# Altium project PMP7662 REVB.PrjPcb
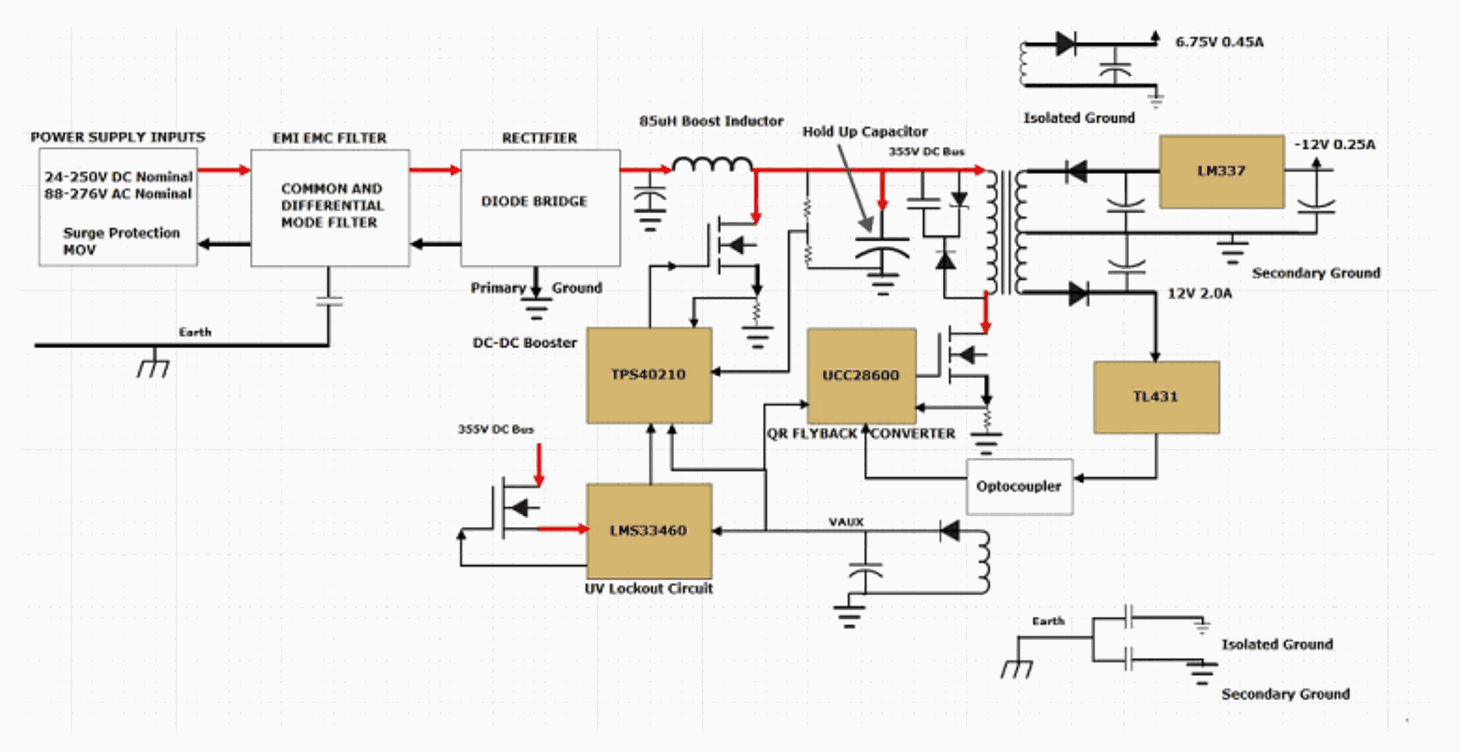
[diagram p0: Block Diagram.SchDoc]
CopyrightYear: 2014; PCB_Rev: A1; PRJ_Customer: Public Release; PRJ_Engineer: Sunil Dwivedi; PRJ_Number: TIDA-00127; PRJ_Title: TIDA-00127-PRPS; SCH_Rev: A1; TechSupport: http://www.ti.com/support
4 sheets, 166 parts. Net scope: flat (ports and power ports of the same name join across sheets).
Board file: PMP7662 REVB-1.PcbDoc
Sheets:
  Block Diagram.SchDoc
  Boost converter.SchDoc
  Fly back converter.SchDoc
  Hardware.SchDoc

## Sheet Block Diagram.SchDoc
size 431 x 279 mm; Date: Not shown in title block; ApprovedBy: Not shown in title block; CheckedBy: Not shown in title block; Author: Not shown in title block; CompanyName: Not shown in title block; Engineer: Not shown in title block; Organization: Not shown in title block; Address1: Not shown in title block; Address2: Not shown in title block; Address3: Not shown in title block; Address4: Not shown in title block; DocumentNumber: 1; Revision: Use project parameter SCH_Rev; SheetNumber: 1; SheetTotal: 4; PageSetup: Record=PageOptions|CenterHorizontal=True|CenterVertical=True|PrintScale=0.96|XCorrection=1.00|YCorrection=1.00|PrintKind=0|BorderSize=5000000|LeftOffset=0|BottomOffset=0|Orientation=2|PaperLength=1000|PaperWidth=1000|Scale=100|PaperSource=15|PrintQuality=600|MediaType=1|DitherType=10|PaperKind=A3|PrintScaleMode=1

## Sheet Boost converter.SchDoc
size 431 x 279 mm; Date: Not shown in title block; ApprovedBy: Not shown in title block; CheckedBy: Not shown in title block; Author: Not shown in title block; CompanyName: Not shown in title block; Engineer: Not shown in title block; Organization: Not shown in title block; Address1: Not shown in title block; Address2: Not shown in title block; Address3: Not shown in title block; Address4: Not shown in title block; DocumentNumber: 2; Revision: Use project parameter SCH_Rev; SheetNumber: 2; SheetTotal: 4; PageSetup: Record=PageOptions|CenterHorizontal=True|CenterVertical=True|PrintScale=1.00|XCorrection=1.00|YCorrection=1.00|PrintKind=0|BorderSize=5000000|LeftOffset=0|BottomOffset=0|Orientation=2|PaperLength=1000|PaperWidth=1000|Scale=100|PaperSource=15|PrintQuality=600|MediaType=1|DitherType=10|PaperKind=Letter|PrintScaleMode=1
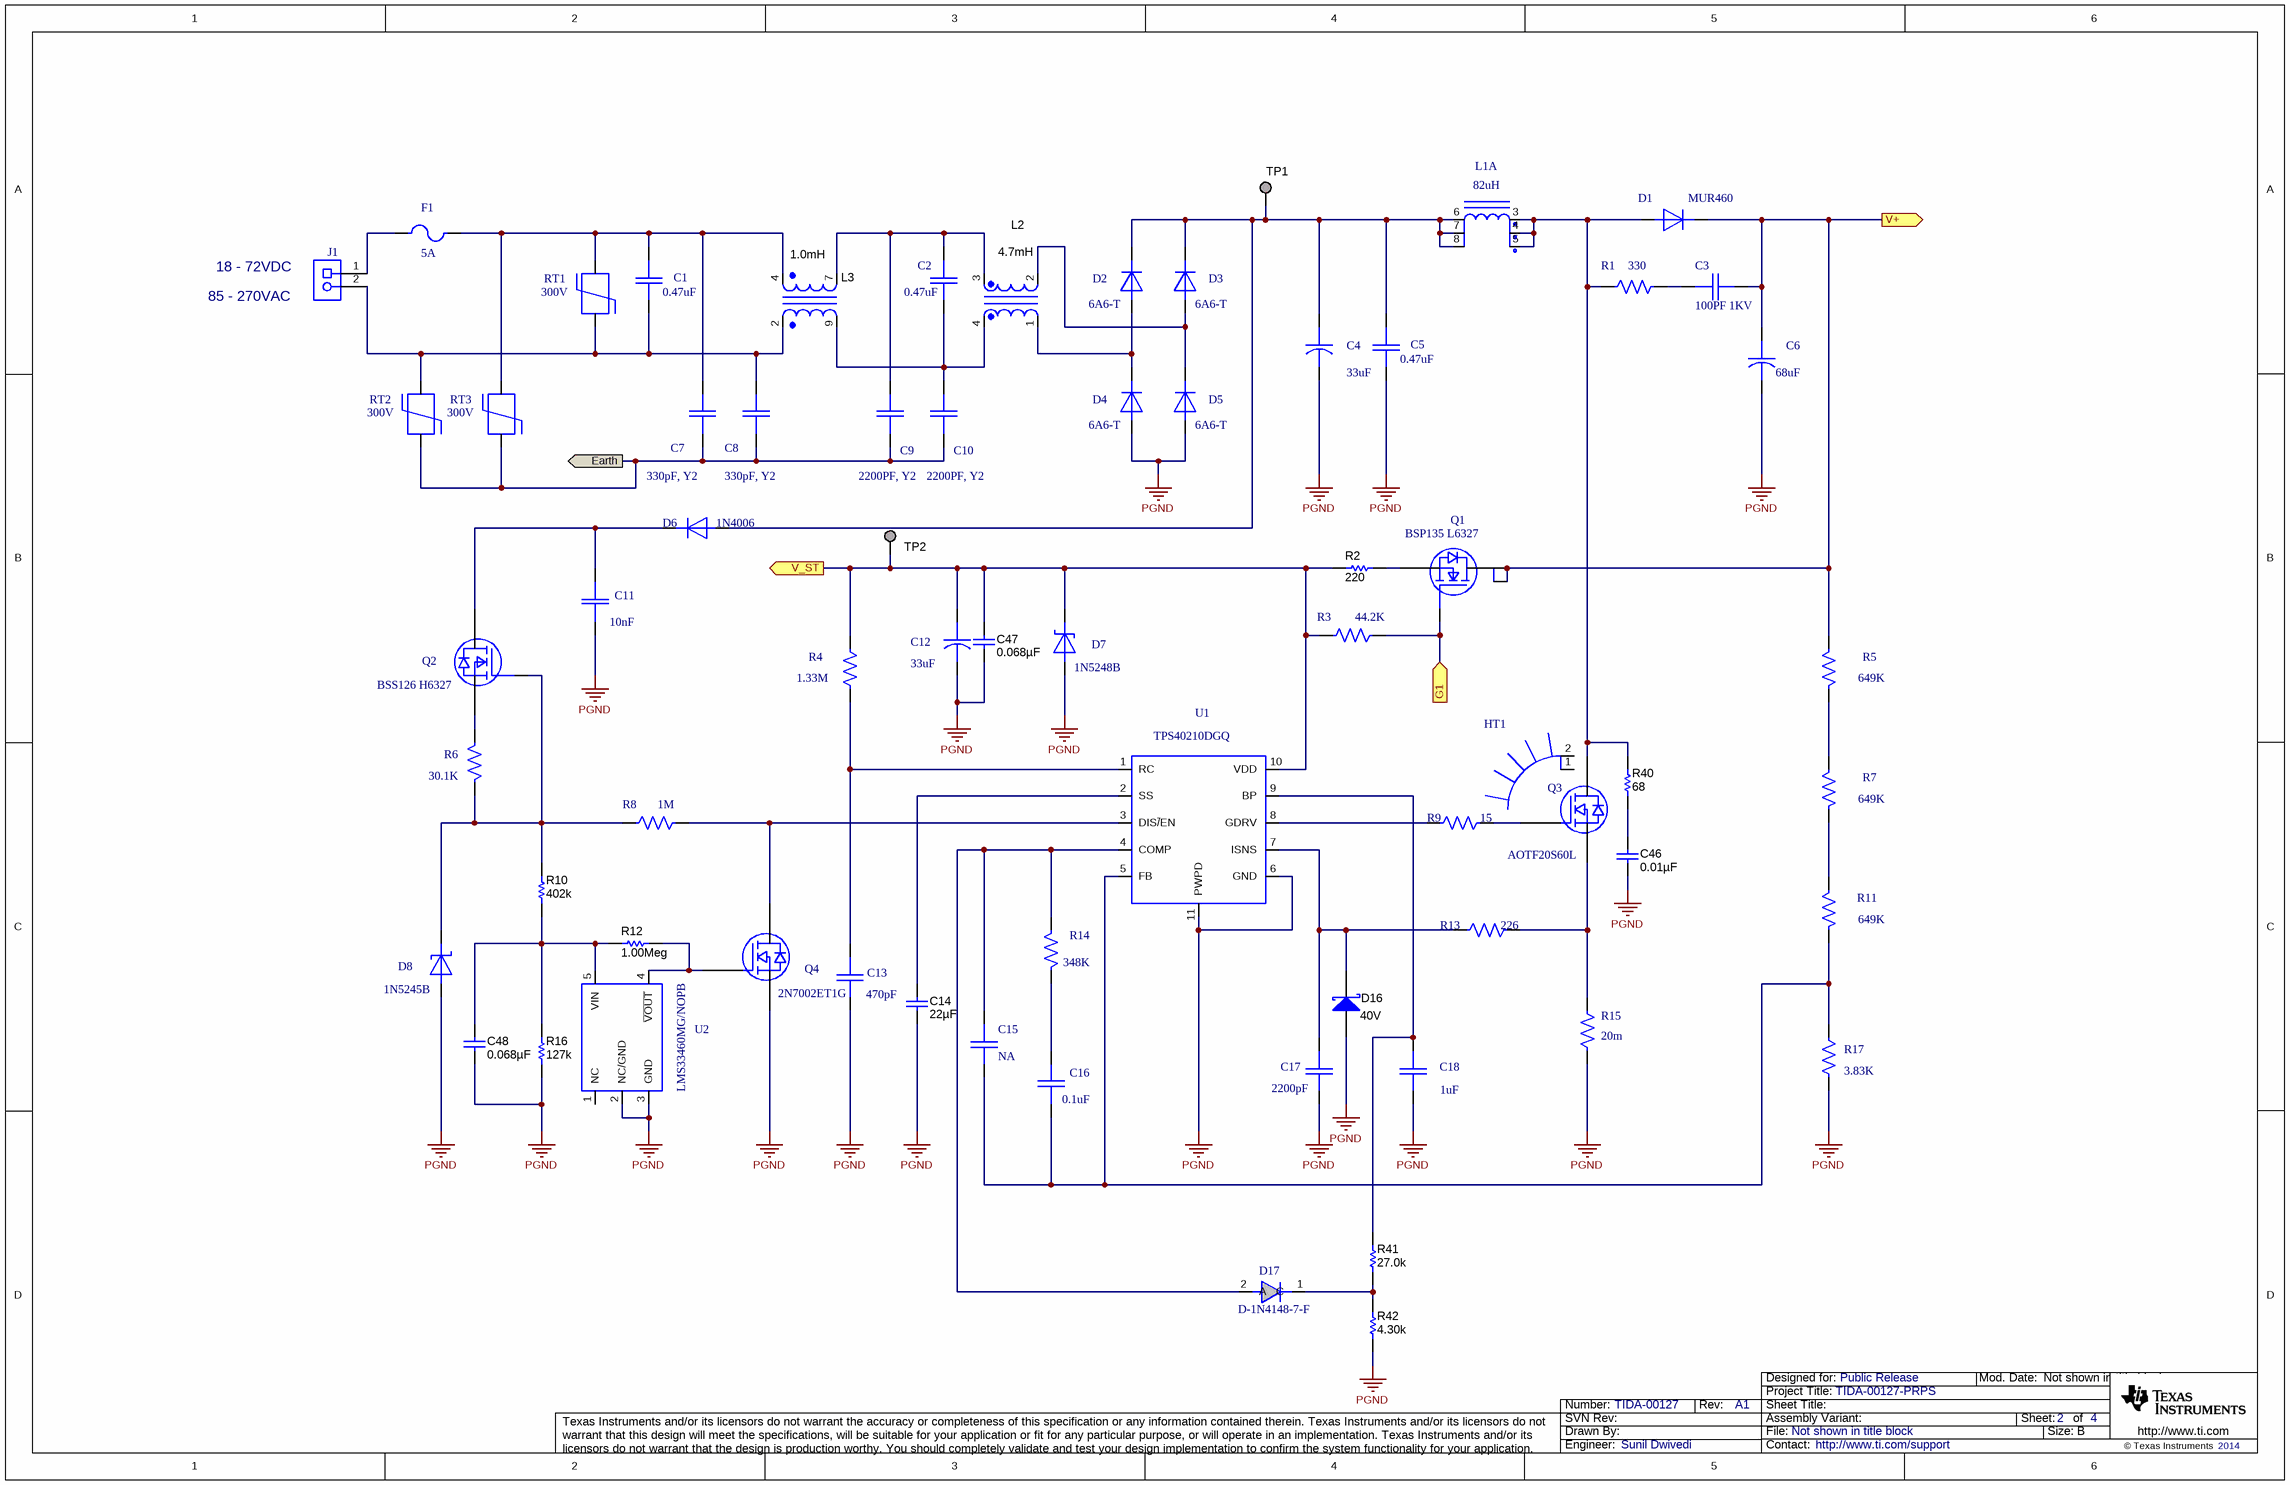
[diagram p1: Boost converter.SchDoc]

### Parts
C1  value 0.47uF  [CAP_591MIL]  (hidden comment: R46KI347050P1M)
C2  value 0.47uF  [CAP_591MIL]  (hidden comment: R46KI347050P1M)
C3  value 100PF 1KV  [CAP_200MIL-A]  (hidden comment: CAP_DE2B3K_7MM_SERIES)
C4  value 33uF  [CAP_16MM_DIA_]  (hidden comment: CAP_EEU-FC1E16_20MM)
C5  value 0.47uF  [CAP_591MIL]  (hidden comment: R46KI347050P1M)
C6  value 68uF  [CAP_EEUFC1H]  (hidden comment: CAP_EEU-FC18_25MM)
C7  value 330pF, Y2  [CAP_DISK_8.4MM]  (hidden comment: CAP_DISK_440_[8.4MM])
C8  value 330pF, Y2  [CAP_DISK_8.4MM]  (hidden comment: CAP_DISK_440_[8.4MM])
C9  value 2200PF, Y2  [CAP_DISK_8.4MM]  (hidden comment: VY2222M35Y5US63V7)
C10  value 2200PF, Y2  [CAP_DISK_8.4MM]  (hidden comment: VY2222M35Y5US63V7)
C11  value 10nF  [CAP_200MIL]  (hidden comment: CAP_ECU-S1HXXKBB)
C12  value 33uF  [CAP_ZL-6.3MM]  (hidden comment: CAP_ZL_6.3MM_SERIES)
C13  value 470pF  [C603]  (hidden comment: C603)
C14  ValueDisplayed: 22µF  [0805_HV]  (hidden comment: C2012X5R1C226K125AC)
C15  value NA  [C603]  (hidden comment: C603)
C16  value 0.1uF  [C603]  (hidden comment: C603)
C17  value 2200pF  [C603]  (hidden comment: C603)
C18  value 1uF  [C603]  (hidden comment: C603)
C46  ValueDisplayed: 0.01µF  [1210]  (hidden comment: GRM32QR73A103KW01L)
C47  ValueDisplayed: 0.068µF  [0603]  (hidden comment: GRM188R71C683KA01D)
C48  ValueDisplayed: 0.068µF  [0603]  (hidden comment: GRM188R71C683KA01D)
D1  value MUR460  [DO-201AD]  (hidden comment: D-MUR4XX_SERIES)
D2  value 6A6-T  [R-6]  (hidden comment: D-6A0X)
D3  value 6A6-T  [R-6]  (hidden comment: D-6A0X)
D4  value 6A6-T  [R-6]  (hidden comment: D-6A0X)
D5  value 6A6-T  [R-6]  (hidden comment: D-6A0X)
D6  value 1N4006  [DO-41]  (hidden comment: D-1N4006)
D7  value 1N5248B  [DO-35]  (hidden comment: D-1N52XXB)
D8  value 1N5245B  [DO-35]  (hidden comment: D-1N52XXB)
D16  value 40V  [SOD-123]  (hidden comment: 1N5819HW-7-F)
D17  D-1N4148-7-F  [D_SOD123]
F1  value 5A  [FUSE_4X8.5-5.08P]  (hidden comment: FUSE_RST_SERIES)
HT1  HEATSINK_PMP1445-HS4  [R2A-CT2-38E-ND]  (value not drawn)
J1  OSTTA024163  [On-Shore_OSTTA024163]  (value not drawn)
L1  value 82uH  [IND_EF25_10P]  (hidden comment: IND_EF25_10P)  (part A of 2)
L2  value 4.7mH  [SS30V]  (hidden comment: SS30V-R350047)
L3  1.0mH  [IND_WE_728_X_1083]
Q1  value BSP135 L6327  [TR_SOT223]  (hidden comment: TR_NFET_SOT223)
Q2  value BSS126 H6327  [SOT-23]  (hidden comment: TR-BSS126)
Q3  value AOTF20S60L  [TO-220V]  (hidden comment: TR-FQPF2N60C)
Q4  value 2N7002ET1G  [SOT-23]  (hidden comment: TR-2N7002)
R1  value 330  [R2512]  (hidden comment: R2512)
R2  value 220  [0603]  (hidden comment: RC0603FR-07220RL)
R3  value 44.2K  [R603]  (hidden comment: R603)
R4  value 1.33M  [R603]  (hidden comment: R603)
R5  value 649K  [R1206]  (hidden comment: R1206)
R6  value 30.1K  [R603]  (hidden comment: R603)
R7  value 649K  [R1206]  (hidden comment: R1206)
R8  value 1M  [R603]  (hidden comment: R603)
R9  value 15  [R0805]  (hidden comment: R0805_1%)
R10  value 402k  [0603]  (hidden comment: CRCW0603402KFKEA)
R11  value 649K  [r1206]  (hidden comment: R1206)
R12  value 1.00Meg  [0603]  (hidden comment: CRCW06031M00FKEA)
R13  value 226  [R603]  (hidden comment: R603)
R14  value 348K  [R603]  (hidden comment: R603)
R15  value 20m  [R2512]  (hidden comment: R2512_1%)
R16  value 127k  [0603]  (hidden comment: CRCW0603127KFKEA)
R17  value 3.83K  [R603]  (hidden comment: R603)
R40  value 68  [2512M]  (hidden comment: RHC2512FT68R0)
R41  value 27.0k  [0603]  (hidden comment: RC0603FR-0727KL)
R42  value 4.30k  [0603]  (hidden comment: RC0603FR-074K3L)
RT1  value 300V  [DISK-472]  (hidden comment: MOV_B72210SXXXXK101)
RT2  value 300V  [DISK-472]  (hidden comment: MOV_B72210SXXXXK101)
RT3  value 300V  [DISK-472]  (hidden comment: MOV_B72210SXXXXK101)
TP1  TESTPOINT  [TESTPOINT]  (value not drawn)  (no BOM)
TP2  TESTPOINT  [TESTPOINT]  (value not drawn)  (no BOM)
U1  TPS40210DGQ  [DGQ_10PWP]
U2  value LMS33460MG/NOPB  [SC-70-5]  (hidden comment: LMS33460)

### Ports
Earth (out), G1, V+, V_ST

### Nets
PGND: C4.2 C5.1 C6.2 C11.1 C12.2 C13.1 C14.2 C17.1 C18.1 C46.2 C47.2 C48.2 D4.2(A) D5.2(A) D7.2(A) D8.2(A) D16.2(A) Q4.2(S) R15.2 R16.2 R17.2 R42.1 U1.6(GND) U1.11(PWPD) U2.2(NC/GND) U2.3(GND)
NetC1_1: C1.1 C8.1 J1.2 L3.2 RT1.1 RT2.2
NetC1_2: C1.2 C7.1 F1.2 L3.4 RT1.2 RT3.2
NetC2_1: C2.1 C10.1 L2.4 L3.9
NetC2_2: C2.2 C9.1 L2.3 L3.7
NetC3_1: C3.1 C6.1 D1.1 Q1.2(D) Q1.4(D) R5.1 ; port V+
NetC3_2: C3.2 R1.2
NetC4_1: C4.1 C5.2 D2.1(C) D3.1(C) D6.2(A) L1.6 L1.7 L1.8 TP1.1
NetC7_2: C7.2 C8.2 C9.2 C10.2 RT2.1 RT3.1 ; port Earth
NetC11_2: C11.2 D6.1(C) Q2.3(D)
NetC12_1: C12.1 C47.1 D7.1(C) R2.1 R3.2 R4.1 TP2.1 U1.10(VDD) ; port V_ST
NetC13_2: C13.2 R4.2 U1.1(RC)
NetC14_1: C14.1 U1.2(SS)
NetC15_1: C15.1 C16.2 R11.2 R17.1 U1.5(FB)
NetC15_2: C15.2 D17.2(A) R14.1 U1.4(COMP)
NetC16_1: C16.1 R14.2
NetC17_2: C17.2 D16.1(K) R13.1 U1.7(ISNS)
NetC18_2: C18.2 R41.2 U1.9(BP)
NetC46_1: C46.1 R40.1
NetC48_1: C48.1 R10.2 R12.1 R16.1 U2.5(VIN)
NetD1_2: D1.2 L1.3 L1.4 L1.5 Q3.2(D) R1.1 R40.2
NetD2_2: D2.2(A) D4.1(C) L2.1
NetD3_2: D3.2(A) D5.1(C) L2.2
NetD8_1: D8.1(C) Q2.1(G) R6.2 R8.1 R10.1
NetD17_1: D17.1(C) R41.1 R42.2
NetF1_1: F1.1 J1.1
NetQ1_1: Q1.1(G) R3.1 ; port G1
NetQ1_3: Q1.3(S) R2.2
NetQ2_2: Q2.2(S) R6.1
NetQ3_1: Q3.1(G) R9.2
NetQ3_3: Q3.3(S) R13.2 R15.1
NetQ4_1: Q4.1(G) R12.2 U2.4(~{VOUT})
NetQ4_3: Q4.3(D) R8.2 U1.3(DIS~{/}EN)
NetR5_2: R5.2 R7.1
NetR7_2: R7.2 R11.1
NetR9_1: R9.1 U1.8(GDRV)

Not connected (* = marked no-connect by the designer): HT1 1 2; U2 1(NC)

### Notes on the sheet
- (near J1) 85 - 270VAC
- (near J1) 18 - 72VDC

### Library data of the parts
C1 C2 C5 = CAP_ECQU2A104XL: CAP FILM 0.47UF 560VDC RADIAL; Manufacturer: Kemet; PCB DECAL: 18.00mm x 9.00mm; Area: 97500
C3 = CAP_DE2B3K_7MM_SERIES: CAP CER 100PF 1KV 10% RADIAL; PartNumber: DEBB33A101KP2A; Manufacturer: muRata; Area: 48.60 mm
C4 = CAP_EEU-FC1E16_20MM: CAP ALUM 33UF 450V 20% RADIAL; Manufacturer: Nichicon; PartNumber: UCS2W330MHD6; PartNumber: Part Number; Type: EKXJ45; Area: 342,119
C6 = CAP_EEU-FC18_25MM: CAP ALUM 68UF 450V 20% RADIAL; Manufacturer: United Chemicon; PartNumber: EKXG451ELL680MMN3S; PartNumber: Part Number; Type: EKXJ45; Area: 428,922
C7 C8 = CAP_DISK_440_[8.4MM]: CAP CER 330PF 300VAC 10% RADIAL; Manufacturer: Vishay; Part_Number: VY2331K29Y5SS63V7; PartNumber: Part Number; Description: Capacitor, 300VAC, X1Y2, ±10%; Area: 103.50 mm; Reference: \\vette02\pmp_pcb\pcad_pdf's\440l.pdf; Second_Source: C:\program files\p-cad 2004\pcad_pdf's\ABB0000CE12.pdf; Type: CAP_DISK_720; Second Source: C:\program files\p-cad2004pcad_pdf's\440l.pdf
C9 C10 = CAP_DISK_440_[8.4MM]: CAP CER 2200PF 300VAC 20% RADIAL; Manufacturer: Vishay
C11 = CAP_ECU-S1HXXKBB: CAP CER 10000PF 1KV 20% RADIAL; Manufacturer: Vishay; PartNumber: S103M47Z5UN63J7R; Part_Number: Part Number; Area: 43200; Reference: \\vette02\pmp_pcb\pcad_pdf's\panasonic_ECQu.pdf; Second_Source: C:\program files\p-cad 2004\pcad_pdf's\panasonic_ECQu.pdf
C12 = CAP_ZL_6.3MM_SERIES: CAP ALUM 33UF 35V 20% RADIAL; Manufacturer: Rubycon; Part_Number: 35YXJ33M5X11; PartNumber: Part Number; Area: 70,686; Type: CAP_ZL_6.3MM SERIES
C13 C15 = C603: CAP CER 470PF 50V 5% NP0 0603; Manufacturer: AVX Corporation; PartNumber: 06035A471JAT2A; Area: 5650
C14 = C2012X5R1C226K125AC: CAP, CERM, 22uF, 16V, +/-10%, X5R, 0805; Manufacturer: TDK; Polarized: N; CompType: Capacitor; U/M: EA; Cap_F: 0.000022; Tolerance_%: 10; Value1: Unknown; VDC_V: 16; TaMin_C: -55; TaMax_C: 85; Cap_Case: 0805
C16 = C603: CAP CER 0.1UF 50V 10% X7R 0603; Manufacturer: Kemet; PartNumber: C0603C104K5RACTU; Area: 5650
C17 = C603: CAP, CERM, 2200pF, 50V, +/-10%, X7R, 0603; Manufacturer: Kemet; Part_Number: Std; PartNumber: C0603C222K5RAC; Area: 5650
C18 = C603: CAP CER 1UF 25V 10% X7R 0603; Manufacturer: Kemet; PartNumber: C0603C105K3RACTU; Area: 5650
C46 = GRM32QR73A103KW01L: CAP, CERM, 0.01uF, 1000V, +/-10%, X7R, 1210; Manufacturer: MuRata; Polarized: N; CompType: Capacitor; U/M: EA; Cap_F: 0.00000001; Tolerance_%: 10; Value1: Unknown; VDC_V: 1000; TaMin_C: -55; TaMax_C: 125
C47 C48 = GRM188R71C683KA01D: CAP, CERM, 0.068uF, 16V, +/-10%, X7R, 0603; Manufacturer: MuRata; Polarized: N; CompType: Capacitor; U/M: EA; Cap_F: 0.000000068; Tolerance_%: 10; Value1: Unknown; VDC_V: 16; TaMin_C: -55; TaMax_C: 125
D1 = D-MUR4XX_SERIES: Diode, Utrafast, Power Rectifier, 600V, 4A; PartNumber: MUR460RLG; Manufacturer: OnSemi; Part_Number: Part Number; Second Source: C:\program files\p-cad 2004\pcad_pdf's\MUR4xx series.pdf; Reference: \\vette02\pmp_pcb\pcad_pdf's\MUR4xx series.pdf; Area: 96800
D2-D5 = D-6A0X: Diode, Rectifier, 600V, 6A; Manufacturer: Diodes; PartNumber: Part Number; Second Source: C:\program files\p-cad 2004\pcad_pdf's\277536,diode.pdf; Reference: \\vette02\pmp_pcb\pcad_pdf's\277536,diode.pdf; Area: 185500
D6 = D-1N4006: Diode, Rectifier, 800V, 1A; PartNumber: 1N4006-T; Manufacturer: Diodes; Part_Number: Part Number; Second Source: C:\program files\p-cad 2004\pcad_pdf's\1N400x.pdf; Reference: \\vette02\pmp_pcb\pcad_pdf's\1N400x.pdf; Area: 54000
D7 = D-1N52XXB: DIODE, Zener, 18V, .5W, 5%; Manufacturer: Fairchild; Part_Number: Part Number; Area: 64900; Second Source: C:\program files\p-cad 2004\pcad_pdf's\1N52xx_DO-35.pdf; Reference: \\vette02\pmp_pcb\pcad_pdf's\1N52xx_DO-35.pdf
D8 = D-1N52XXB: DIODE, Zener, 15V, .5W, 5%; PartNumber: 1N5245BTR; Manufacturer: Fairchild; Area: 64900; Second Source: C:\program files\p-cad 2004\pcad_pdf's\1N52xx_DO-35.pdf; Reference: \\vette02\pmp_pcb\pcad_pdf's\1N52xx_DO-35.pdf
D16 = 1N5819HW-7-F: Diode, Schottky, 40V, 1A, SOD-123; Manufacturer: Diodes Inc.; U/M: EA; Vf_V: 0.45; Value2: 0.45V; Io_A: 1; Vr_V: 40; TJmax_C: 125
D17 = D-1N4148-7-F: Diode, Signal, 300-mA, 75-V, 350-mW; PartNumber: 1N4148W-7-F; Manufacturer: Diodes; Area: 13300; Value: 1N4148W-7-F
F1 = FUSE_RST_SERIES: FUSE SLOW 250VAC 5A RADIAL; Manufacturer: BEL; PartNumber: RST 5; Area: 43.2 mm; Reference: \\vette02\pmp_pcb\pcad_pdf's\RST.pdf; Second Source: C:\program files\p-cad 2004\pcad_pdf's\RST.pdf
HT1 = HEATSINK_R2A-CT2-38E: Heatsink, TO-220; Manufacturer: Ohmite; PartNumber: Part Number
J1 = OSTTA024163: Terminal Block, 2x1, 5.08mm, TH; PartNumber: OSTTC022162; Manufacturer: On-Shore Technology; SymbolCreator: a0412235; U/M: EA
L1 = IND_EF25_10P: Inductor, 82uH; Manufacturer: WE; PartNumber: 750342278; Area: 1000000
L2 = IND_SS30V-R350047: Inductor, Power Choke SS30V; Manufacturer: Kemet
L3 = IND_744824622: CHOKE TOROID 1.0mH 10A VERT; PartNumber: 744824101; Manufacturer: WE; Area: 997500
Q1 = TR_NFET_SOT223: MOSFET N-CH 600V 120MA SOT-223; Manufacturer: Infineon; Second Source: C:\program files\p-cad 2004\pcad_pdf's\BSS126.pdf; Reference: \\vette02\pmp_pcb\pcad_pdf's\BSS126.pdf; Area: 86400
Q2 = TR-BSS126: MOSFET N-CH 600V 21MA SOT23; Manufacturer: Infineon; Second Source: C:\program files\p-cad 2004\pcad_pdf's\BSS126.pdf; Reference: \\vette02\pmp_pcb\pcad_pdf's\BSS126.pdf; Area: 14105
Q3 = TR-FQPF2N60C: MOSFET, Nch, 600-V, 20A, 0.199 Ohms; Manufacturer: Alpha&Omega; Area: 65.4 mm; Reference: \\vette02\pmp_pcb\pcad_pdf's\FQPF2N60C.pdf; Second Source: C:\program files\p-cad 2004\pcad_pdf's\FQPF2N60C.pdf
Q4 = TR-2N7002: MOSFET N-CH 60V 260MA SOT-23; Manufacturer: OnSemi; Second Source: C:\program files\p-cad 2004\pcad_pdf's\Diodes_2n7002.pdf; Reference: \\vette02\pmp_pcb\pcad_pdf's\Diodes_2n7002.pdf; Area: 14105
R1 = R2512: RES 330 OHM 1W 5% 2512; Manufacturer: Samsung; PartNumber: RC6432J331CS; Area: 35100
R2 = RC0603FR-07220RL: RES, 220 ohm, 1%, 0.1W, 0603; Manufacturer: Yageo America; CompType: Resistor; Value_Code: 220R; Tolerance_%: 1; Power_W: 0.1; VDC_V: 150; TempCo: 200 ppm/C; U/M: EA
R3 = R603: RES 44.2K OHM 1/10W 1% 0603 SMD; Part_Number: RC0603FR-0744K2L; Manufacturer: Yageo; Area: 5650
R4 = R603: RES 1.33M OHM 1/10W 1% 0603 SMD; Part_Number: CRCW06031M33FKEA; Manufacturer: Vishay Dale; Area: 5650
R5 R7 R11 = R1206: RES 649K OHM 1/4W 1% 1206 SMD; Manufacturer: Yageo; PartNumber: RC1206FR-07649KL; Area: 15390
R6 = R603: RES 30.1K OHM 1/10W 1% 0603 SMD; Part_Number: RC0603FR-0730K1L; Manufacturer: Yageo; Area: 5650
R8 = R603: RES 1.00M OHM 1/10W 1% 0603 SMD; Part_Number: RC0603FR-071ML; Manufacturer: Yageo; Area: 5650
R9 = R0805_1%: RES 15.0 OHM 1/8W 1% 0805 SMD; Part_Number: RC0805FR-0715RL; Manufacturer: Yageo; Area: 15,300
R10 = CRCW0603402KFKEA: RES, 402k ohm, 1%, 0.1W, 0603; Manufacturer: Vishay-Dale; CompType: Resistor; Res_ohm: 402000; Tolerance_%: 1; Power_W: 0.1; VDC_V: 75; TempCo: 100 ppm/C; EIA_Code: E96; U/M: EA
R12 = CRCW06031M00FKEA: RES, 1.00Meg ohm, 1%, 0.1W, 0603; Manufacturer: Vishay-Dale; CompType: Resistor; Res_ohm: 1000000; Value_Code: 1M00; Tolerance_%: 1; Power_W: 0.1; VDC_V: 75; TempCo: 100 ppm/C; EIA_Code: E96; U/M: EA
R13 = R603: RES 226 OHM 1/10W 1% 0603 SMD; Part_Number: RC0603FR-07226RL; Manufacturer: Yageo; Area: 5650
R14 = R603: RES 348K OHM 1/10W 1% 0603 SMD; Part_Number: RC0603FR-07348KL; Manufacturer: Yageo; Area: 5650
R15 = R2512_1%: RES 0.02 OHM 1W 1% 2512 SMD; Part_Number: LRMAM2512-R02FT4; Manufacturer: TT/Welwyn; Area: 56000; Second Source: C:\program files\p-cad 2004\pcad_pdf's\SML-LXR1206USBC-TR[1].pdf; Reference: \\vette02\pmp_pcb\pcad_pdf's\SML-LXR1206USBC-TR[1].pdf
R16 = CRCW0603127KFKEA: RES, 127k ohm, 1%, 0.1W, 0603; Manufacturer: Vishay-Dale; CompType: Resistor; Res_ohm: 127000; Tolerance_%: 1; Power_W: 0.1; VDC_V: 75; TempCo: 100 ppm/C; EIA_Code: E96; U/M: EA
R17 = R603: RES 3.83K OHM 1/10W 1% 0603 SMD; Part_Number: RC0603FR-073K83L; Manufacturer: Yageo; Area: 5650
R40 = CRCW251222R0JNEGHP: RES 68 OHM 2W 1% 2512; Manufacturer: Stackpole Electronics Inc; CompType: Resistor; Tolerance_%: 1
R41 = RC0603FR-0727KL: RES, 27.0k ohm, 1%, 0.1W, 0603; Manufacturer: Yageo America; CompType: Resistor; Res_ohm: 27000; Value_Code: 27k0; Tolerance_%: 1; Power_W: 0.1; VDC_V: 150; TempCo: 200 ppm/C; U/M: EA
R42 = RC0603FR-074K3L: RES, 4.30k ohm, 1%, 0.1W, 0603; Manufacturer: Yageo America; CompType: Resistor; Res_ohm: 4300; Value_Code: 4k30; Tolerance_%: 1; Power_W: 0.1; VDC_V: 150; TempCo: 200 ppm/C; U/M: EA
RT1-RT3 = MOV_B72210SXXXXK101: MOV, 300V; Manufacturer: Bourns; Part_Number: MOV-10D471KTR; Area: 85,500
TP1 TP2 = TESTPOINT: TEST POINT.  No entry in BOM.; PartNumber: Part Number
U1 = TPS40210DGQ: IC REG CTRLR BST FLYBK CM 10MSOP; Manufacturer: TI; PartNumber: TPS40210DGQR; Area: 38400; Reference: \\vette02\pmp_pcb\pcad_pdf's\tps40210.pdf; Second Source: C:\program files\p-cad 2004\pcad_pdf's\tps40210.pdf
U2 = LMS33460: IC DETECTOR UNDER VOLT 3V SC70-5; Manufacturer: TI; Second Source: C:\program files\p-cad 2004\pcad_pdf's\lms33460[1].pdf; Reference: \\vette02\pmp_pcb\pcad_pdf's\lms33460[1].pdf; Area: 12.05 mm

## Sheet Fly back converter.SchDoc
size 431 x 279 mm; Date: Not shown in title block; ApprovedBy: Not shown in title block; CheckedBy: Not shown in title block; Author: Not shown in title block; CompanyName: Not shown in title block; Engineer: Not shown in title block; Organization: Not shown in title block; Address1: Not shown in title block; Address2: Not shown in title block; Address3: Not shown in title block; Address4: Not shown in title block; DocumentNumber: 3; Revision: Use project parameter SCH_Rev; SheetNumber: 3; SheetTotal: 4; PageSetup: Record=PageOptions|CenterHorizontal=True|CenterVertical=True|PrintScale=1.00|XCorrection=1.00|YCorrection=1.00|PrintKind=0|BorderSize=5000000|LeftOffset=0|BottomOffset=0|Orientation=2|PaperLength=1000|PaperWidth=1000|Scale=100|PaperSource=15|PrintQuality=600|MediaType=1|DitherType=10|PaperKind=Letter|PrintScaleMode=1
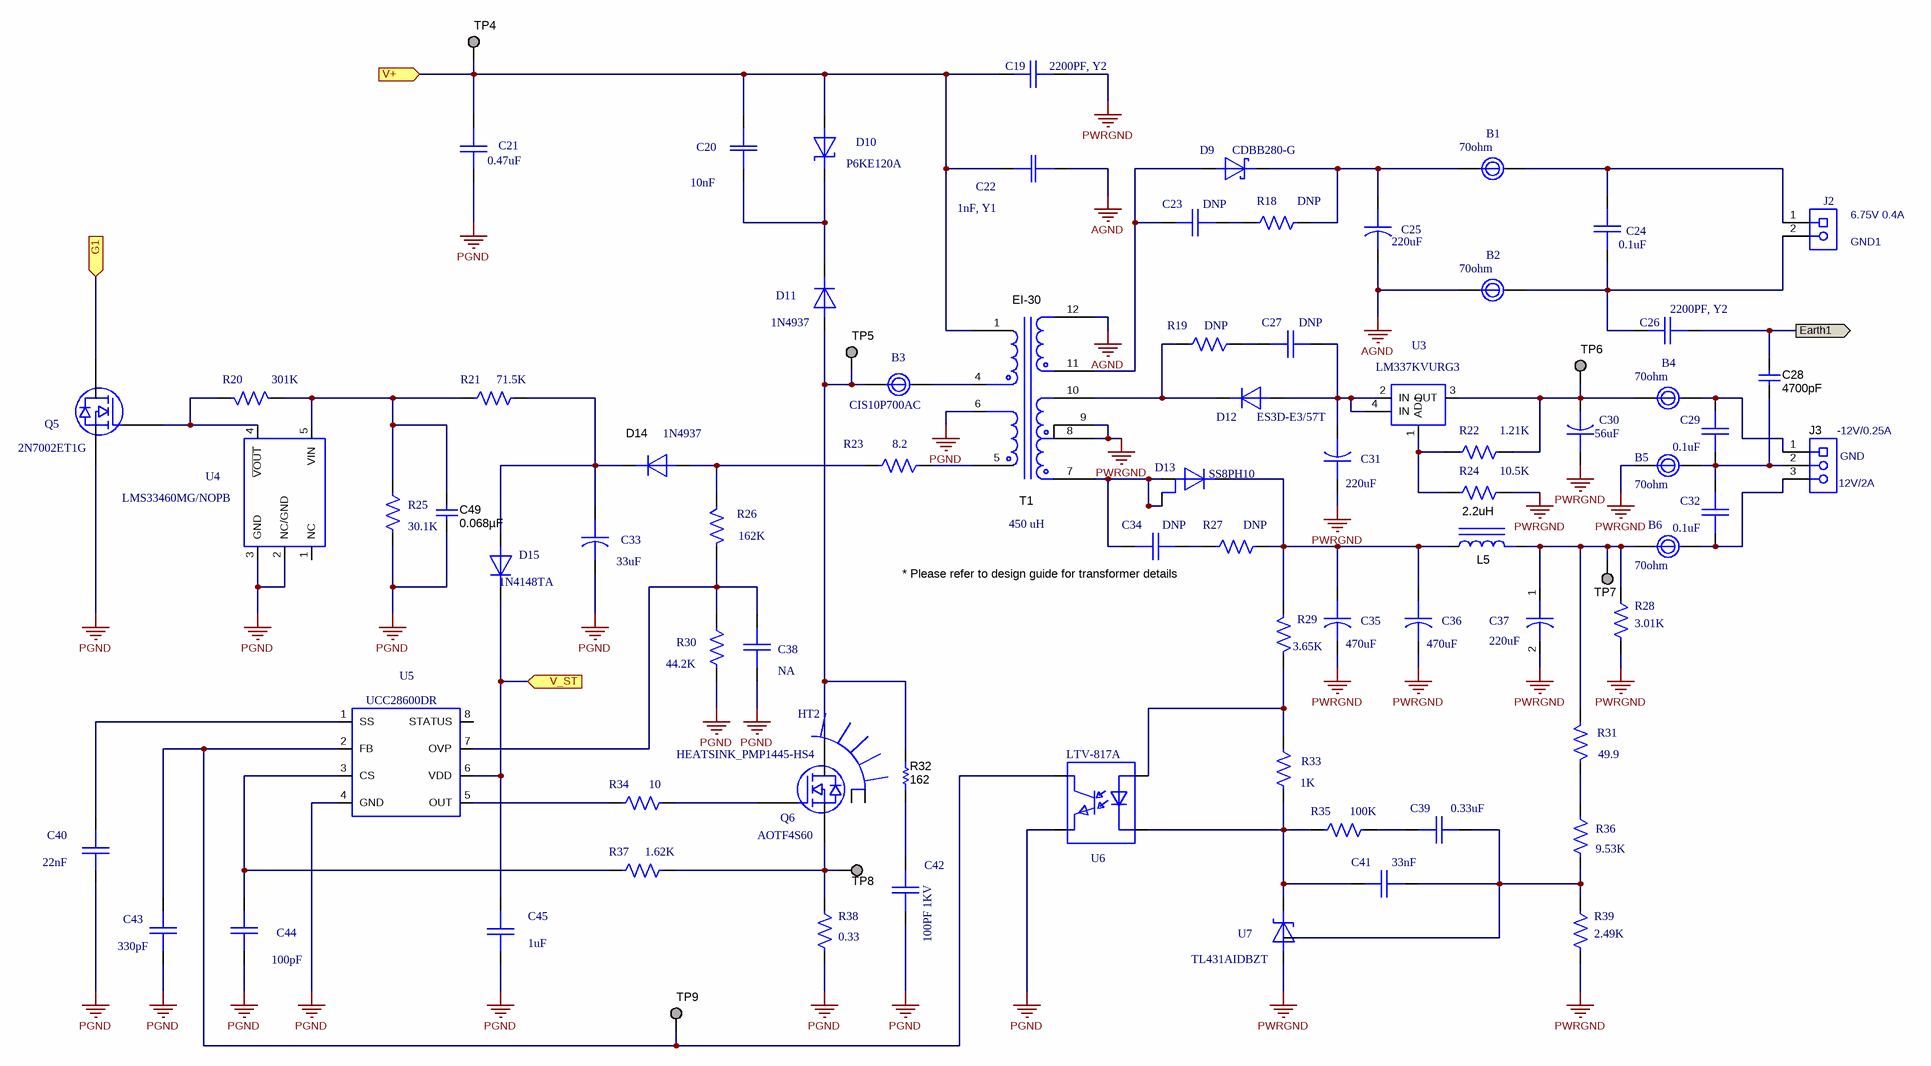
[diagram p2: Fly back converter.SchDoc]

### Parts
B1  value 70ohm  [0603]  (hidden comment: BEAD-BLM18AG_SERIES)
B2  value 70ohm  [0603]  (hidden comment: BEAD-BLM18AG_SERIES)
B3  CIS10P700AC  [0603]
B4  value 70ohm  [0603]  (hidden comment: BEAD-BLM18AG_SERIES)
B5  value 70ohm  [0603]  (hidden comment: BEAD-BLM18AG_SERIES)
B6  value 70ohm  [0603]  (hidden comment: BEAD-BLM18AG_SERIES)
C19  value 2200PF, Y2  [CAP_DISK_8.4MM]  (hidden comment: VY2222M35Y5US63V7)
C20  value 10nF  [CAP_200MIL]  (hidden comment: CAP_ECU-S1HXXKBB)
C21  value 0.47uF  [CAP_591MIL]  (hidden comment: R46KI347050P1M)
C22  value 1nF, Y1  [CAP_DISK_720]  (hidden comment: CAP_DISK_720)
C23  value DNP  [c603]  (hidden comment: C603)
C24  value 0.1uF  [C603]  (hidden comment: C603)
C25  value 220uF  [CAP_ALUM-10MM]  (hidden comment: CAP_EKZE_10MM_SERIES)
C26  value 2200PF, Y2  [CAP_DISK_8.4MM]  (hidden comment: VY2222M35Y5US63V7)
C27  value DNP  [C603]  (hidden comment: C603)
C28  ValueDisplayed: 4700pF  [1812]  (hidden comment: 1812GC472KAT1A)
C29  value 0.1uF  [C603]  (hidden comment: C603)
C30  value 56uF  [CAP_ZL-6.3MM]  (hidden comment: CAP_ZL_6.3MM_SERIES)
C31  value 220uF  [CAP_ALUM-10MM]  (hidden comment: CAP_EKZE_10MM_SERIES)
C32  value 0.1uF  [C603]  (hidden comment: C603)
C33  value 33uF  [CAP_ZL-6.3MM]  (hidden comment: CAP_ZL_6.3MM_SERIES)
C34  value DNP  [C0805]  (hidden comment: C0805)
C35  value 470uF  [CAP_ALUM-10MM]  (hidden comment: CAP_EKZE_10MM_SERIES)
C36  value 470uF  [CAP_ALUM-10MM]  (hidden comment: CAP_EKZE_10MM_SERIES)
C37  value 220uF  [CAP_ALUM-10MM]  (hidden comment: CAP_ALUM_FC-F)
C38  value NA  [C603]  (hidden comment: C603)
C39  value 0.33uF  [C603]  (hidden comment: C603)
C40  value 22nF  [c603]  (hidden comment: C603)
C41  value 33nF  [C603]  (hidden comment: C603)
C42  value 100PF 1KV  [CAP_200MIL-A]  (hidden comment: CAP_DE2B3K_7MM_SERIES)
C43  value 330pF  [c603]  (hidden comment: C603)
C44  value 100pF  [c603]  (hidden comment: C603)
C45  value 1uF  [c603]  (hidden comment: C603)
C49  ValueDisplayed: 0.068µF  [0603]  (hidden comment: GRM188R71C683KA01D)
D9  value CDBB280-G  [MOT_SMB_CASE]  (hidden comment: D_SCHOT_SMB)
D10  value P6KE120A  [DO-204AC]  (hidden comment: D_P6KEXXX)
D11  value 1N4937  [DO-41_VERT]  (hidden comment: D-1N4006)
D12  value ES3D-E3/57T  [DO-214AB]  (hidden comment: D-ES3D)
D13  value SS8PH10  [TO-277[SMPC]]  (hidden comment: D-S4P_SERIES)
D14  value 1N4937  (hidden comment: D-1N4006)
D15  value 1N4148TA  [DO-35]  (hidden comment: D-1N4148MSCT)
HT2  HEATSINK_PMP1445-HS4  [R2A-CT2-38E-ND]
J2  OSTTA024163  [On-Shore_OSTTA024163]  (value not drawn)
J3  OSTTA034163  [On-Shore_OSTTA034163]  (value not drawn)
L5  2.2uH  [IND_200_MIL]
Q5  value 2N7002ET1G  [SOT-23]  (hidden comment: TR-2N7002)
Q6  value AOTF4S60  [TO-220V]  (hidden comment: TR-FQPF2N60C)
R18  value DNP  [R2512]  (hidden comment: R2512)
R19  value DNP  [R2512]  (hidden comment: R2512)
R20  value 301K  [r603]  (hidden comment: R603)
R21  value 71.5K  [r603]  (hidden comment: R603)
R22  value 1.21K  [R603]  (hidden comment: R603)
R23  value 8.2  [R1206]  (hidden comment: R1206)
R24  value 10.5K  [R603]  (hidden comment: R603)
R25  value 30.1K  [r603]  (hidden comment: R603)
R26  value 162K  [r603]  (hidden comment: R603)
R27  value DNP  [R2512]  (hidden comment: R2512)
R28  value 3.01K  [R603]  (hidden comment: R603)
R29  value 3.65K  [R603]  (hidden comment: R603)
R30  value 44.2K  [r603]  (hidden comment: R603)
R31  value 49.9  [R603]  (hidden comment: R603)
R32  value 162  [2512M]  (hidden comment: CRCW2512162RFKEGHP)
R33  value 1K  [R603]  (hidden comment: R603)
R34  value 10  [r0805]  (hidden comment: R0805_1%)
R35  value 100K  [R603]  (hidden comment: R603)
R36  value 9.53K  [R603]  (hidden comment: R603)
R37  value 1.62K  [r603]  (hidden comment: R603)
R38  value 0.33  [2010]  (hidden comment: R2010)
R39  value 2.49K  [R603]  (hidden comment: R603)
T1  EI-30  value 450 uH  [XFMR-EI30-10PIN-VER-TEMP]
TP4  TESTPOINT  [TESTPOINT]  (value not drawn)  (no BOM)
TP5  TESTPOINT  [TESTPOINT]  (value not drawn)  (no BOM)
TP6  TESTPOINT  [TESTPOINT]  (value not drawn)  (no BOM)
TP7  TESTPOINT  [TESTPOINT]  (value not drawn)  (no BOM)
TP8  TESTPOINT  [TESTPOINT]  (value not drawn)  (no BOM)
TP9  TESTPOINT  [TESTPOINT]  (value not drawn)  (no BOM)
U3  value LM337KVURG3  [KTE]  (hidden comment: LM337KTER)
U4  value LMS33460MG/NOPB  [SC-70-5]  (hidden comment: LMS33460)
U5  UCC28600DR  [SO8]
U6  LTV-817A  [DIP-4A]
U7  value TL431AIDBZT  [SOT-23]  (hidden comment: TL431AIDBZ)

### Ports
Earth1 (out), G1, V+, V_ST

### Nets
AGND: B2.1 C22.1 C25.2 T1.12
PGND: C21.1 C33.2 C38.2 C40.1 C42.2 C43.2 C44.2 C45.1 C49.2 Q5.2(S) R25.2 R30.2 R38.2 T1.6 U4.2(NC/GND) U4.3(GND) U5.4(GND) U6.3(E)
PWRGND: B5.1 C19.2 C30.1 C31.1 C35.2 C36.2 C37.2 R24.2 R28.2 R39.2 T1.8 T1.9 U7.3(A)
NetB1_1: B1.1 C25.1 D9.1(C) R18.2
NetB1_2: B1.2 C24.1 J2.1
NetB2_2: B2.2 C24.2 C26.1 J2.2
NetB3_1: B3.1 D11.2(A) Q6.2(D) R32.2 TP5.1
NetB3_2: B3.2 T1.4
NetB4_1: B4.1 C30.2 R22.2 TP6.1 U3.3(OUT)
NetB4_2: B4.2 C29.1 J3.1
NetB5_2: B5.2 C28.2 C29.2 C32.1 J3.2
NetB6_1: B6.1 C37.1 L5.2 R28.1 R31.2 TP7.1
NetB6_2: B6.2 C32.2 J3.3
NetC3_1: C19.1 C20.2 C21.2 C22.2 D10.2(A) T1.1 TP4.1 ; port V+
NetC12_1: C45.2 D15.1(C) U5.6(VDD) ; port V_ST
NetC20_1: C20.1 D10.1(C) D11.1(C)
NetC23_1: C23.1 D9.2(A) T1.11
NetC23_2: C23.2 R18.1
NetC26_2: C26.2 C28.1 ; port Earth1
NetC27_1: C27.1 C31.2 D12.2(A) U3.2(IN) U3.4(IN)
NetC27_2: C27.2 R19.1
NetC33_1: C33.1 D14.2(C) D15.2(A) R21.2
NetC34_1: C34.1 R27.1
NetC34_2: C34.2 D13.1 D13.2(A) T1.7
NetC35_1: C35.1 C36.1 D13.3(C) L5.1 R27.2 R29.2
NetC38_1: C38.1 R26.2 R30.1 U5.7(OVP)
NetC39_1: C39.1 C41.2 R36.2 R39.1 U7.2(REF)
NetC39_2: C39.2 R35.2
NetC40_2: C40.2 U5.1(SS)
NetC41_1: C41.1 R33.2 R35.1 U6.2(C) U7.1(C)
NetC42_1: C42.1 R32.1
NetC43_1: C43.1 TP9.1 U5.2(FB) U6.4(C)
NetC44_1: C44.1 R37.1 U5.3(CS)
NetC49_1: C49.1 R20.1 R21.1 R25.1 U4.5(VIN)
NetD12_1: D12.1(C) R19.2 T1.10
NetD14_1: D14.1(A) R23.2 R26.1
NetQ1_1: Q5.3(D) ; port G1
NetQ5_1: Q5.1(G) R20.2 U4.4(~{VOUT})
NetQ6_1: Q6.1(G) R34.2
NetQ6_3: Q6.3(S) R37.2 R38.1 TP8.1
NetR22_1: R22.1 R24.1 U3.1(ADJ)
NetR23_1: R23.1 T1.5
NetR29_1: R29.1 R33.1 U6.1(A)
NetR31_1: R31.1 R36.1
NetR34_1: R34.1 U5.5(OUT)

Not connected (* = marked no-connect by the designer): HT2 1 2; U4 1(NC); U5 8(STATUS)

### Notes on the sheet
- (near J2) 6.75V 0.4A
- (near J2) GND1
- (near J3) -12V/0.25A
- (near J3) 12V/2A
- (near J3) GND
- * Please refer to design guide for transformer details

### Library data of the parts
B1 B2 B5 B6 = BEAD-BLM18AG_SERIES: FERRITE CHIP 70 OHM 4000MA 0603; Manufacturer: Samsung; PartNumber: CIS10P700AC; Second Source: C:\program files\p-cad 2004\pcad_pdf's\Bead BML SERIES.pdf; Reference: \\vette02\pmp_pcb\pcad_pdf's\Bead BML SERIES.pdf; Area: 5.87 mm
B3 = BEAD-BLM18AG_SERIES: FERRITE CHIP 70 OHM 4000MA 0603; Manufacturer: Samsung; Second Source: C:\program files\p-cad 2004\pcad_pdf's\Bead BML SERIES.pdf; Reference: \\vette02\pmp_pcb\pcad_pdf's\Bead BML SERIES.pdf; Area: 5.87 mm; Value: 70ohm
B4 = BEAD-BLM18AG_SERIES: FERRITE CHIP 70 OHM 4000MA 0603; Manufacturer: Samsung; PartNumber: CIS10P700AC; Part_Number: Part Number; Second Source: C:\program files\p-cad 2004\pcad_pdf's\Bead BML SERIES.pdf; Reference: \\vette02\pmp_pcb\pcad_pdf's\Bead BML SERIES.pdf; Area: 5.87 mm
C19 C26 = CAP_DISK_440_[8.4MM]: as C9 on sheet Boost converter
C20 = CAP_ECU-S1HXXKBB: as C11 on sheet Boost converter
C21 = CAP_ECQU2A104XL: as C1 on sheet Boost converter
C22 = CAP_DISK_720: CAP CER 1000PF 500VAC 20% RADIAL; Manufacturer: Vishay; PartNumber: VY1102M35Y5UQ63V0; Area: 189800; Reference: \\vette02\pmp_pcb\pcad_pdf's\ABB0000CE12.pdf; Second_Source: C:\program files\p-cad 2004\pcad_pdf's\ABB0000CE12.pdf
C23 C27 = C603: CAP CER 330PF 250V 5% NP0 0603; Manufacturer: TDK; PartNumber: C1608C0G2E331J080AA; Area: 5650
C24 C29 C32 = C603: as C16 on sheet Boost converter
C25 C31 = CAP_EKZE_10MM_SERIES: CAP ALUM 220UF 35V 20% RADIAL; Manufacturer: Panasonic; Area: 96.42 mm; Type: EEU-FM1V221L; Second Source: C:\program files\p-cad 2004\pcad_pdf's\ekze_cap.pdf; Reference: \\vette02\pmp_pcb\pcad_pdf's\ekze_cap.pdf
C28 = 1812GC472KA1: CAP, CERM, 4700pF, 2000V, +/-10%, X7R, 1812; Manufacturer: AVX; Polarized: N; CompType: Capacitor; U/M: EA; Cap_F: 0.0000000047; Tolerance_%: 10; Value1: Unknown; VDC_V: 2000; TaMin_C: -55; TaMax_C: 125
C30 = CAP_ZL_6.3MM_SERIES: CAP ALUM 56UF 35V 20% RADIAL; Manufacturer: Nichicon; PartNumber: UHE1V560MED; Area: 70,686; Type: CAP_ZL_6.3MM SERIES
C33 = CAP_ZL_6.3MM_SERIES: CAP ALUM 33UF 35V 20% RADIAL; Manufacturer: Rubycon; Part_Number: 35YXJ33M5X11; Area: 70,686; Type: CAP_ZL_6.3MM SERIES
C34 = C0805: CAP CER 1000PF 250V 5% NP0 0603; Manufacturer: TDK; Part_Number: C1608C0G2E102J080AA; Area: 10560; Type: CAP_ECQ-E2104KB
C35 C36 = CAP_EKZE_10MM_SERIES: CAP ALUM 470UF 35V 20% RADIAL; Manufacturer: Panasonic; Part_Number: EEU-FM1V471; Part_Number: Part Number; Area: 96.42 mm; Second Source: C:\program files\p-cad 2004\pcad_pdf's\ekze_cap.pdf; Reference: \\vette02\pmp_pcb\pcad_pdf's\ekze_cap.pdf
C37 = CAP_ALUM_FC-F: CAP ALUM 220UF 25V 20% RADIAL; Manufacturer: United Chemicon; Part_Number: EKY-250ELL221MHB5D; Area: 144480; Voltage: 16V
C38 = C603: CAP CERAMIC, 25V, C0G, 10%; Manufacturer: STD; Area: 5650
C39 = C603: CAP CER 0.33UF 25V 10% X7R 0603; Manufacturer: TDK; PartNumber: C1608X7R1E334K080AC; Area: 5650
C40 = C603: CAP CER 0.022UF 50V 10% X7R 0603; Manufacturer: Kemet; PartNumber: C0603C223K5RACTU; Area: 5650
C41 = C603: CAP CER 0.033UF 50V 10% X7R 0603; Manufacturer: AVX Corporation; Part_Number: 06035C333KAT2A; Area: 5650
C42 = CAP_DE2B3K_7MM_SERIES: as C3 on sheet Boost converter
C43 = C603: CAP CER 330PF 50V 5% NP0 0603; Manufacturer: AVX Corporation; Part_Number: 06035A331JAT2A; Area: 5650
C44 = C603: CAP CER 100PF 50V 10% NP0 0603; Manufacturer: AVX Corporation; Part_Number: Std; PartNumber: 06035A101KAT2A; Area: 5650
C45 = C603: as C18 on sheet Boost converter
C49 = GRM188R71C683KA01D: as C47 on sheet Boost converter
D9 = D_SCHOT_SMB: Diode, Schottky, 2-A, 80-V; Manufacturer: MCC; Area: 95000
D10 = D_P6KEXXX: DIODE,Transient Voltage Suppressor,120V, 600W; Manufacturer: Littelfuse; Second Source: C:\program files\p-cad 2004\pcad_pdf's\P6KE200_datasheet.pdf; Reference: \\vette02\pmp_pcb\pcad_pdf's\P6KE200_datasheet.pdf; Area: 134300
D11 = D-1N4006: Diode, Fast, 600V, 1A; Manufacturer: Fairchild; Part_Number: Part Number; Second Source: C:\program files\p-cad 2004\pcad_pdf's\1N400x.pdf; Reference: \\vette02\pmp_pcb\pcad_pdf's\1N400x.pdf; Area: 54000
D12 = D-ES3D: Diode, Rectifier, Trr 20 ns, Vrrm 200V, 3A; Manufacturer: Fairchild; Second Source: C:\program files\p-cad 2004\pcad_pdf's\ds14003.pdf; Reference: \\vette02\pmp_pcb\pcad_pdf's\ds14003.pdf; Area: 95000
D13 = D-S4P_SERIES: Diode Schottky, 8A, 100V; PartNumber: SS8PH10-M3/86A; Manufacturer: Vishay; Area: 73600; Second Source: C:\program files\p-cad 2004\pcad_pdf's\s4pm[1].pdf; Reference: \\vette02\pmp_pcb\pcad_pdf's\s4pm[1].pdf
D14 = D-1N4006: Diode, Fast, 600V, 1A; Manufacturer: Fairchild; Part_Number: Part Number; Second Source: C:\program files\p-cad 2004\pcad_pdf's\1N400x.pdf; Reference: \\vette02\pmp_pcb\pcad_pdf's\1N400x.pdf; Area: 54000; PCB DECAL: DO-41_VERT
D15 = D-1N4148MSCT: Diode, Signal, 200-mA, 100-V, 350-mW; Manufacturer: Fairchild; Area: 40000; Second_Source: C:\program files\p-cad 2004\pcad_pdf's\1N400x.pdf; Reference: \\vette02\pmp_pcb\pcad_pdf's\1N4148.pdf; Type: D-1N4006; Second Source: C:\program files\p-cad 2004\pcad_pdf's\1N4148.pdf
HT2 = HEATSINK_R2A-CT2-38E: as HT1 on sheet Boost converter
J2 = OSTTA024163: as J1 on sheet Boost converter
J3 = OSTTA034163: Terminal Block, 3x1, 5.08 mm, TH; PartNumber: OSTTC032162; Manufacturer: On-Shore Technology; SymbolCreator: a0412235; U/M: EA
L5 = IND_RFB0807_SERIES: INDUCTOR 2.2UH 4.1A RADIAL; Manufacturer: Taiyo Yuden; Part_Number: LHL08TB2R2M; Area: 113411; Type: PD2 744
Q5 = TR-2N7002: as Q4 on sheet Boost converter
Q6 = TR-FQPF2N60C: MOSFET, Nch, 600-V, 4A, 0.9 Ohms; Manufacturer: Alpha&Omega; Area: 65.4 mm; Reference: \\vette02\pmp_pcb\pcad_pdf's\FQPF2N60C.pdf; Second Source: C:\program files\p-cad 2004\pcad_pdf's\FQPF2N60C.pdf
R18 R19 = R2512: RES 33 OHM 1W 5% 2512; Manufacturer: Samsung; PartNumber: RC6432J330CS; Area: 35100
R20 = R603: RES 301K OHM 1/10W 1% 0603 SMD; Part_Number: RC0603FR-07301KL; Manufacturer: Yageo; Area: 5650
R21 = R603: RES 71.5K OHM 1/10W 1% 0603 SMD; Part_Number: RC0603FR-0771K5L; Manufacturer: Yageo; Area: 5650
R22 = R603: RES 1.21K OHM 1/10W 1% 0603 SMD; Part_Number: RC0603FR-071K21L; Manufacturer: Yageo; Area: 5650; Description: RES 1.37K OHM 1/10W 1% 0603 SMD
R23 = R1206: RES 8.20 OHM 1/4W 1% 1206 SMD; Part_Number: RC1206FR-078R2L; Manufacturer: Yageo; Area: 15390
R24 = R603: RES 10.5K OHM 1/10W 1% 0603 SMD; Part_Number: Std; Manufacturer: Yageo; PartNumber: RC0603FR-0710K5L; Part_Number: Part Number; Area: 5650
R25 = R603: as R6 on sheet Boost converter
R26 = R603: RES 162K OHM 1/10W 1% 0603 SMD; Part_Number: RC0603FR-07162KL; Manufacturer: Yageo; Area: 5650
R27 = R2512: RES 8.20 OHM 1W 5% 2512; Manufacturer: TE Connectivity; PartNumber: 6-1622820-6; Area: 35100
R28 = R603: RES 3.01K OHM 1/10W 1% 0603 SMD; Part_Number: RC0603FR-073K01L; Manufacturer: Yageo; Area: 5650
R29 = R603: RES 3.65K OHM 1/10W 1% 0603 SMD; Part_Number: RC0603FR-073K65L; Manufacturer: Yageo; Area: 5650
R30 = R603: as R3 on sheet Boost converter
R31 = R603: RES 49.9 OHM 1/10W 1% 0603 SMD; Part_Number: RC0603FR-0749R9L; Manufacturer: Yageo; Area: 5650
R32 = CRCW2512332RFKEG: RES 162 OHM 1.5W 1% 2512 SMD; Manufacturer: Vishay-Dale; CompType: Resistor; Value_Code: 162R; Tolerance_%: 1; EIA_Code: E96; U/M: EA
R33 = R603: RES 1.00K OHM 1/10W 1% 0603 SMD; Part_Number: RC0603FR-071KL; Manufacturer: Yageo; Area: 5650
R34 = R0805_1%: RES 10.0 OHM 1/8W 1% 0805 SMD; Part_Number: RC0805FR-0710RL; Manufacturer: Yageo; Area: 15,300
R35 = R603: RES 100K OHM 1/10W 1% 0603 SMD; Manufacturer: Yageo; PartNumber: RC0603FR-07100KL; Area: 5650
R36 = R603: RES 9.53K OHM 1/10W 1% 0603 SMD; Part_Number: RC0603FR-079K53L; Manufacturer: Yageo; Area: 5650
R37 = R603: RES 1.62K OHM 1/10W 1% 0603 SMD; Part_Number: RC0603FR-071K62L; Manufacturer: Yageo; Area: 5650
R38 = R2010: RES 0.33 OHM 1W 1% 2010; Part_Number: CSRN2010FKR330; Manufacturer: Stackpole; Area: 30800; Second Source: C:\program files\p-cad 2004\pcad_pdf's\SML-LXR1206USBC-TR[1].pdf; Reference: \\vette02\pmp_pcb\pcad_pdf's\SML-LXR1206USBC-TR[1].pdf
R39 = R603: RES 2.49K OHM 1/10W 1% 0603 SMD; Part_Number: Std; Manufacturer: Yageo; PartNumber: RC0603FR-072K49L; Part_Number: Part Number; Area: 5650
T1 = XFMR_750811190: Transformer, EI-30, Vertical; Manufacturer: Wurth; PartNumber: 750342279; Second Source: C:\program files\p-cad 2004\pcad_pdf's\750811190.pdf; Reference: \\vette02\pmp_pcb\pcad_pdf's\750811190.pdf; Area: 546000; PCB DECAL: XFMR_WE_567X876
TP4-TP9 = TESTPOINT: as TP1 on sheet Boost converter
U3 = LM337KTER: IC REG LDO NEG ADJ 1.5A TO252; Manufacturer: TI; Second Source: C:\program files\p-cad 2004\pcad_pdf's\lm337.pdf; Reference: \\vette02\pmp_pcb\pcad_pdf's\lm337.pdf; Area: 192700
U4 = LMS33460: as U2 on sheet Boost converter
U5 = UCC28600D: IC CTRLR PWM GREEN CM OVP 8SOIC; Manufacturer: TI; Area: 75900; Reference: \\vette02\pmp_pcb\pcad_pdf's\ucc28600.pdf; Second_Source: C:\program files\p-cad 2004\pcad_pdf's\UCC28610_PreLim_DataSheet.doc; Second Source: C:\program files\p-cad 2004\pcad_pdf's\ucc28600.pdf
U6 = OPTO_PS2513-1: OPTOCOUPLER TRANS 5KVRMS 4DIP; Manufacturer: Lite-On; Area: 81901; Reference: \\vette02\pmp_pcb\pcad_pdf's\ps2513.pdf; Second_Source: C:\program files\p-cad 2004\pcad_pdf's\ps2513.pdf
U7 = TL431AIDBZ: IC VREF SHUNT PREC ADJ SOT23-3; Manufacturer: TI; Second Source: C:\program files\p-cad 2004\pcad_pdf's\TL431A-B.pdf; Reference: \\vette02\pmp_pcb\pcad_pdf's\TL431A-B.pdf; Area: 16384

## Sheet Hardware.SchDoc
size 431 x 279 mm; Date: Not shown in title block; ApprovedBy: Not shown in title block; CheckedBy: Not shown in title block; Author: Not shown in title block; CompanyName: Not shown in title block; Engineer: Not shown in title block; Organization: Not shown in title block; Address1: Not shown in title block; Address2: Not shown in title block; Address3: Not shown in title block; Address4: Not shown in title block; DocumentNumber: 4; Revision: Use project parameter SCH_Rev; SheetNumber: 4; SheetTotal: 4; PageSetup: Record=PageOptions|CenterHorizontal=True|CenterVertical=True|PrintScale=1.00|XCorrection=1.00|YCorrection=1.00|PrintKind=0|BorderSize=5000000|LeftOffset=0|BottomOffset=0|Orientation=2|PaperLength=1000|PaperWidth=1000|Scale=100|PaperSource=15|PrintQuality=600|MediaType=1|DitherType=10|PaperKind=Letter|PrintScaleMode=1
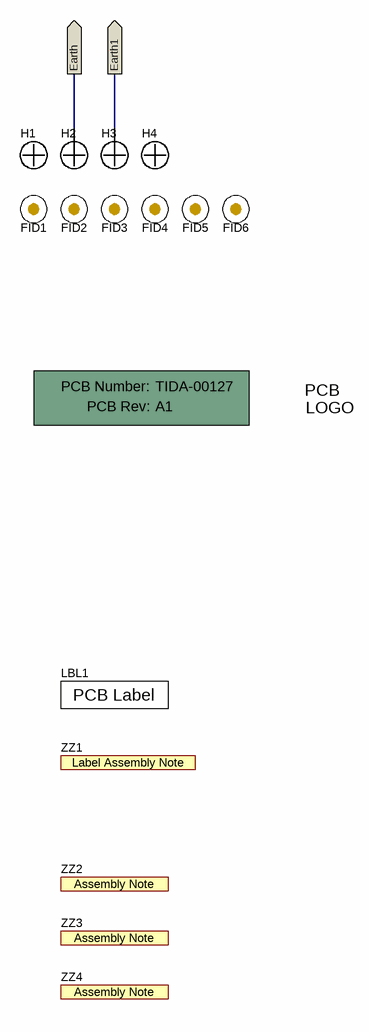
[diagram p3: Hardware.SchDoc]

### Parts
!PCB1  (no value)  (mechanical)
FID1  Fiducial  [Fiducial10-20]  (value not drawn)
FID2  Fiducial  [Fiducial10-20]  (value not drawn)
FID3  Fiducial  [Fiducial10-20]  (value not drawn)
FID4  Fiducial  [Fiducial10-20]  (value not drawn)
FID5  Fiducial  [Fiducial10-20]  (value not drawn)
FID6  Fiducial  [Fiducial10-20]  (value not drawn)
H1  (no value)  [NY PMS 440 0025 PH]
H2  (no value)  [NY PMS 440 0025 PH]
H3  (no value)  [NY PMS 440 0025 PH]
H4  (no value)  [NY PMS 440 0025 PH]
LBL1  (no value)  [Label_650x200]
Logo1  (no value)  [TI_Stacked_SolderMask_Small]  (no BOM)
ZZ1  (no value)  [AssemblyNoteLabel]  (no BOM)
ZZ2  (no value)  [AssemblyNote]  (no BOM)
ZZ3  (no value)  [AssemblyNote]  (no BOM)
ZZ4  (no value)  [AssemblyNote]  (no BOM)

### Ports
Earth1 (out), Earth (out)

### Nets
NetC7_2: H2.1 ; port Earth
NetC26_2: H3.1 ; port Earth1

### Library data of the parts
!PCB1 = PCB: Printed Circuit Board; Manufacturer: Any; PartNumber: TIDA-00127; Part_Number: Part Number; SymbolCreator: a0412235
FID1-FID6 = Fiducial: Fiducial mark.  There is nothing to buy or mount.; Part_Number: Part Number; SymbolCreator: codlsc
H1-H4 = NY PMS 440 0025 PH: Mounting Hole M3 3.5mm; Manufacturer: STD; CompType: Hardware; U/M: EA
LBL1 = THT-14-423-10: Thermal Transfer Printable Labels, 0.650" W x 0.200" H - 10,000 per roll; Manufacturer: Brady; Part_Number: Part Number; SymbolCreator: a0412235; CompType: Label; Note: Size: 0.65" x 0.20 "
Logo1 = TI_Logo: Texas Instrument Corporate Signature; Part_Number: Part Number; SymbolCreator: codlsc
ZZ1 = AssemblyNoteLabel: This Assembly Note is for PCB labels only; Part_Number: Part Number; SymbolCreator: a0412235
ZZ2 = AssemblyNote: These assemblies are ESD sensitive, ESD precautions shall be observed.; Part_Number: Part Number; SymbolCreator: codlsc
ZZ3 = AssemblyNote: These assemblies must be clean and free from flux and all contaminants. Use of no clean flux is not acceptable.; Part_Number: Part Number; SymbolCreator: codlsc
ZZ4 = AssemblyNote: These assemblies must comply with workmanship standards IPC-A-610 Class 2, unless otherwise specified.; Part_Number: Part Number; SymbolCreator: codlsc

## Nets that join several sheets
PGND: Boost converter (26 pins), Fly back converter (18 pins)
NetC3_1: Boost converter (6 pins), Fly back converter (7 pins)
NetC7_2: Boost converter (6 pins), Hardware (H2.1)
NetC12_1: Boost converter (8 pins), Fly back converter (C45.2 D15.1 U5.6)
NetC26_2: Fly back converter (C26.2 C28.1), Hardware (H3.1)
NetQ1_1: Boost converter (Q1.1 R3.1), Fly back converter (Q5.3)

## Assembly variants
001: not fitted C15 C23 C27 C34 C38 C48 C49 R18 R19 R27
